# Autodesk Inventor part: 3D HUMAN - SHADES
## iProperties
Category: PART
Company: Cross Bros.
Shininess: 64.0
Length Units: 11272
Angle Units: 11279
Time Units: 11290
Mass Units: 11286
Length Display Precision: 3
Angle Display Precision: 2
Compacted: True
Part Number: 3D HUMAN - SHADES
Document SubType Name: Modeling
Created: 2003-03
Designer: MVF
Catalog Web Link: www.crossbros.com
Density: 0.0
Volumn: 0.0
Area: 0.0
PropertySet Name: Model Information
Control State: 0
Master: False
Checked Out: False
Author: MVF
Title: iMike
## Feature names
1. Extrusion1
2. Mirror1
3. Extrusion2
4. Fillet1
5. Extrusion3
6. Fillet2
7. Mirror2
8. Fillet3
9. Fillet4
